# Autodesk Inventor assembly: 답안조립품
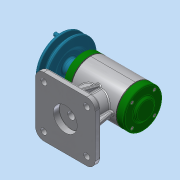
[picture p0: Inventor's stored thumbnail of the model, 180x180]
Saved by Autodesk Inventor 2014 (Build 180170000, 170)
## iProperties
Created: 2021-08
Part Number: 답안조립품
Document SubType Name: Assembly
Designer: dg
Mass: 1893.46 g
Surface Area: 1471.4 cm^2
Volume: 474.558 cm^3
Density: 3.98995 g/cm^3
Author: dg
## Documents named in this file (20)
- C:\Users\dg\Desktop\610806V1007\답안조립품.iam
- C:\Users\dg\Desktop\610806V1007\본체.ipt
- C:\Users\dg\Desktop\610806V1007\본체커버.ipt
- C:\Users\dg\Desktop\610806V1007\개스킷.ipt
- C:\Users\dg\Desktop\610806V1007\앞커버.ipt
- C:\Users\dg\Desktop\610806V1007\뒤커버.ipt
- C:\Users\dg\Desktop\610806V1007\베어링 6202.ipt
- C:\Users\dg\Desktop\610806V1007\베어링 6201.ipt
- C:\Users\dg\Desktop\610806V1007\편심축.ipt
- C:\Users\dg\Desktop\610806V1007\오일 실 12 22 7.ipt
- 오일 실 12 22 7.ipt
- C:\Users\dg\Desktop\610806V1007\키 4x4x18.ipt
- 키 4x4x18.ipt
- C:\Users\dg\Desktop\610806V1007\V-벨트풀리.ipt
- C:\Users\dg\Desktop\610806V1007\멈춤나사 M3x8.ipt
- C:\Users\dg\Desktop\610806V1007\볼트 M3x0.5x8.ipt
- C:\Users\dg\Desktop\610806V1007\슬라이드.ipt
- C:\Users\dg\Desktop\610806V1007\와셔.ipt
- C:\Users\dg\Desktop\610806V1007\볼트 M6 x 12.ipt
- C:\Users\dg\Desktop\610806V1007\가변스프링.ipt
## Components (4 placed, 3 different names)
1. 개스킷:1
2. 개스킷:2
3. V-벨트풀리:1
4. 가변스프링:1
